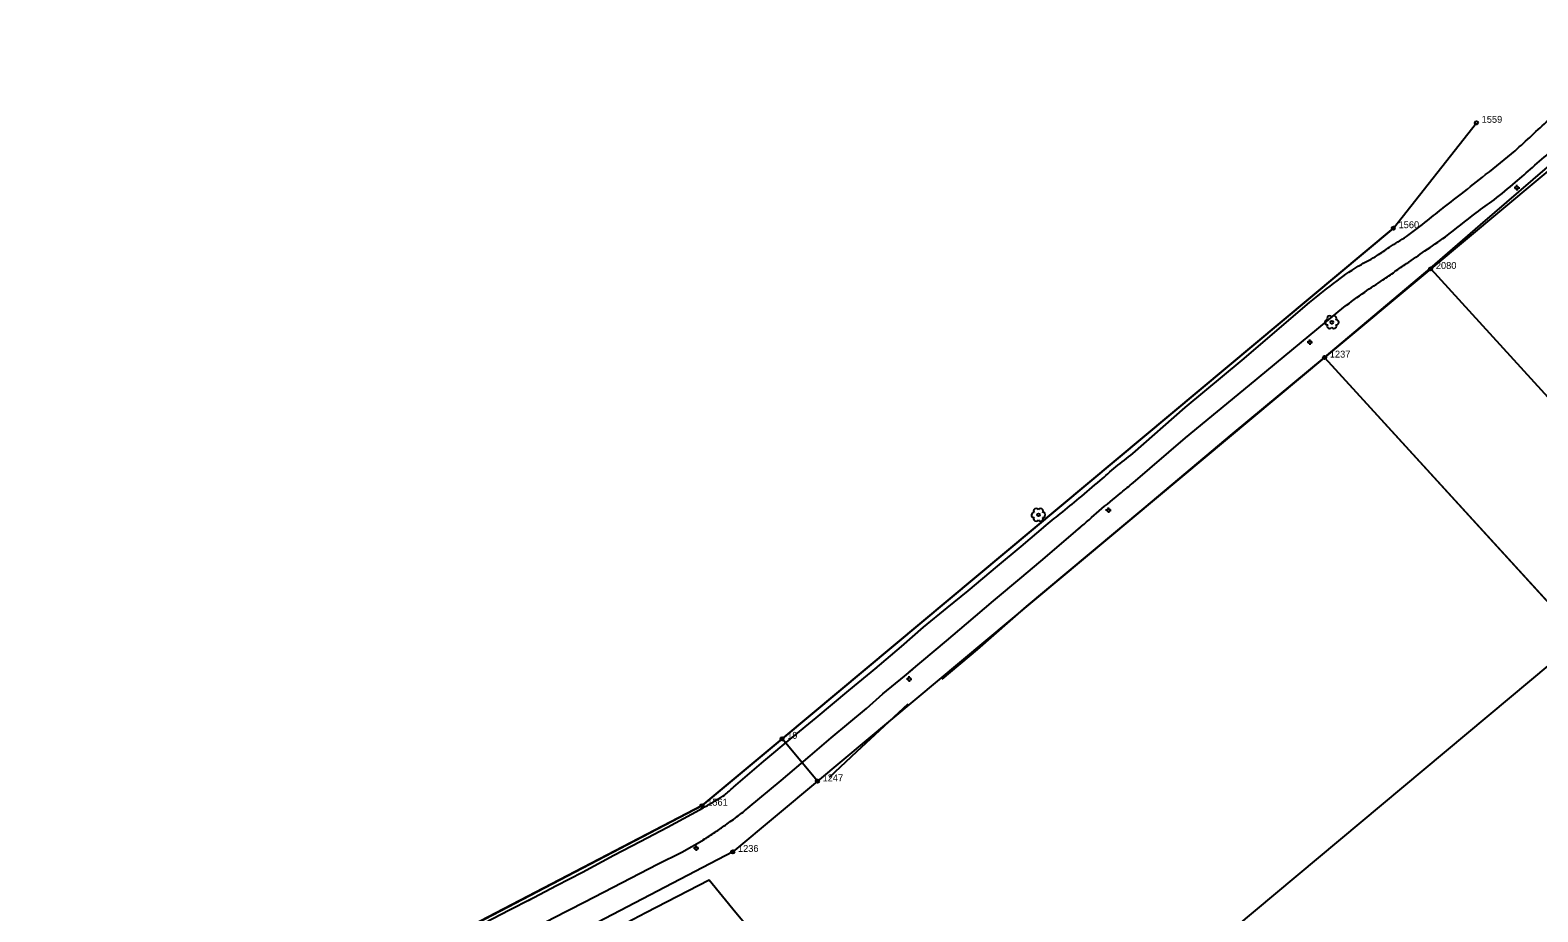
# Model space of a CAD drawing. Extents: x 1517693 to 1518189, y 6494860 to 6495280.
# Drawn here: x 1517718.2 to 1517936.6, y 6495102.4 to 6495230.1 of the extents above; entities that cross this region are included whole.
import ezdxf

# ---------------------------------------------------------------- set-up
doc = ezdxf.new("R2010")
doc.units = 0
for name, color, linetype in [('gc_vag', 7, 'Continuous'), ('grans', 7, 'Continuous'), ('granspunkt', 7, 'Continuous'), ('granspunkt_text', 7, 'Continuous'), ('hack', 7, 'Continuous'), ('kvartersgrans', 7, 'Continuous'), ('kvartersgrans_utan_fastgr', 7, 'Continuous'), ('lovtrad', 7, 'Continuous'), ('staket', 7, 'Continuous'), ('stolpe_belysning', 7, 'Continuous')]:
    doc.layers.add(name, color=color, linetype=linetype)

msp = doc.modelspace()

# ---------------------------------------------------------------- linework, layer by layer
at = {"layer": 'gc_vag'}
for points in [[(1517877.91, 6495168.79), (1517885.48, 6495175.44), (1517893.74, 6495182.28), (1517903.48, 6495190.65)], [(1517877.95, 6495164.55), (1517885.53, 6495171.07), (1517894.79, 6495178.7), (1517908.48, 6495189.97)], [(1517840.59, 6495137.59), (1517844.4, 6495140.81), (1517847.59, 6495143.61), (1517851, 6495146.4), (1517854.04, 6495148.9), (1517858.32, 6495152.45), (1517861.73, 6495155.32), (1517865.28, 6495158.33)], [(1517845.55, 6495137.12), (1517850.93, 6495141.65), (1517853.83, 6495144.08), (1517857.74, 6495147.41), (1517861.84, 6495150.86), (1517865.21, 6495153.72), (1517869.67, 6495157.53), (1517870.39, 6495158.15)], [(1517820.06, 6495120.45), (1517824.46, 6495124.2), (1517828.56, 6495127.61), (1517832.04, 6495130.48), (1517836.79, 6495134.43), (1517840.81, 6495137.77)], [(1517822.19, 6495117.44), (1517826.97, 6495121.41), (1517831.17, 6495124.97), (1517834.22, 6495127.58), (1517839.33, 6495131.82), (1517841.72, 6495133.96), (1517844.83, 6495136.53), (1517845.99, 6495137.48)], [(1517790.33, 6495104.03), (1517794.43, 6495106.16), (1517798.2, 6495108.12), (1517802.73, 6495110.59), (1517806.54, 6495112.54), (1517810.49, 6495114.65), (1517815.16, 6495117.15)], [(1517789.99, 6495099.37), (1517794, 6495101.48), (1517798.46, 6495103.77), (1517802.62, 6495105.94), (1517809.04, 6495109.25), (1517812.59, 6495111.02), (1517815.82, 6495112.87)], [(1517764.88, 6495090.69), (1517769.35, 6495093.03), (1517773.3, 6495095.1), (1517776.31, 6495096.66), (1517781.06, 6495099.2), (1517783.99, 6495100.76), (1517787.62, 6495102.64), (1517790.66, 6495104.2)]]:
    msp.add_lwpolyline(points, dxfattribs=at)
for points in [[(1517908.48, 6495189.97), (1517911.48, 6495192.18), (1517914.11, 6495193.92), (1517915.85, 6495195.13), (1517917.53, 6495196.29), (1517920.21, 6495198.13), (1517923.16, 6495200.18), (1517927.63, 6495203.66), (1517930.21, 6495205.55), (1517933.32, 6495208.08), (1517935.79, 6495210.24), (1517938.53, 6495212.61), (1517940.37, 6495214.19), (1517943, 6495216.82), (1517944.9, 6495218.45)], [(1517922.49, 6495204.07), (1517925.48, 6495206.4), (1517929, 6495209.19), (1517933.26, 6495212.66), (1517938.11, 6495217.09), (1517939.63, 6495218.4)], [(1517903.48, 6495190.65), (1517907.48, 6495193.81), (1517911, 6495196.18), (1517913.27, 6495197.45), (1517915.06, 6495198.66), (1517917.53, 6495200.24), (1517920.58, 6495202.55), (1517922.9, 6495204.4)], [(1517865.07, 6495158.15), (1517867.4, 6495160.05), (1517870.12, 6495162.3), (1517873.16, 6495164.87), (1517875.45, 6495166.83), (1517877.91, 6495168.79)], [(1517870.11, 6495157.91), (1517873.02, 6495160.45), (1517876.24, 6495163.13), (1517877.95, 6495164.55)], [(1517814.84, 6495116.98), (1517816.51, 6495117.91), (1517817.74, 6495118.64), (1517818.75, 6495119.29), (1517820.06, 6495120.45)], [(1517815.66, 6495112.78), (1517817.41, 6495113.92), (1517818.9, 6495114.94), (1517820.75, 6495116.28), (1517822.6, 6495117.77)]]:
    msp.add_spline(points, degree=3, dxfattribs=at)
at = {"layer": 'grans'}
for p, q in [((1517962.44, 6495230.13), (1517921.04, 6495195.52)), ((1517915.64, 6495201.43), (1517927.67, 6495216.7)), ((1517827.1, 6495127.44), (1517915.64, 6495201.43)), ((1517921.04, 6495195.52), (1517905.68, 6495182.68)), ((1517905.68, 6495182.68), (1517832.22, 6495121.28)), ((1517905.68, 6495182.68), (1517942.78, 6495142.01)), ((1517942.78, 6495142.01), (1517887.66, 6495095.94)), ((1517815.51, 6495117.75), (1517827.1, 6495127.44)), ((1517832.22, 6495121.28), (1517827.1, 6495127.44)), ((1517832.22, 6495121.28), (1517819.97, 6495111.05)), ((1517760.41, 6495089.02), (1517815.51, 6495117.75)), ((1517819.97, 6495111.05), (1517718.21, 6495058))]:
    msp.add_line(p, q, dxfattribs=at)
at = {"layer": 'granspunkt'}
for centre in [(1517927.67, 6495216.7), (1517915.64, 6495201.43), (1517921.04, 6495195.52), (1517905.68, 6495182.68), (1517827.1, 6495127.44), (1517832.22, 6495121.28), (1517815.51, 6495117.75), (1517819.97, 6495111.05)]:
    msp.add_circle(centre, 0.237, dxfattribs=at)
at = {"layer": 'hack'}
msp.add_line((1517928.27, 6495201.92), (1517939.69, 6495211.77), dxfattribs=at)
for points in [[(1517905.67, 6495182.7), (1517920.95, 6495195.6), (1517928.27, 6495201.92)], [(1517879.54, 6495160.85), (1517892.35, 6495171.65), (1517905.67, 6495182.7)], [(1517862.49, 6495146.61), (1517868.38, 6495151.53), (1517879.54, 6495160.85)], [(1517850.27, 6495136.09), (1517855.4, 6495140.4), (1517862.49, 6495146.61)], [(1517845.3, 6495132.45), (1517841.19, 6495128.65), (1517837.9, 6495125.54), (1517833.91, 6495121.81)]]:
    msp.add_lwpolyline(points, dxfattribs=at)
at = {"layer": 'kvartersgrans'}
for p, q in [((1517962.44, 6495230.13), (1517921.04, 6495195.52)), ((1517915.64, 6495201.43), (1517927.67, 6495216.7)), ((1517819.97, 6495111.05), (1517718.21, 6495058))]:
    msp.add_line(p, q, dxfattribs=at)
for points in [[(1517915.64, 6495201.43), (1517827.1, 6495127.44), (1517815.51, 6495117.75), (1517760.41, 6495089.02)], [(1517905.68, 6495182.68), (1517832.22, 6495121.28), (1517819.97, 6495111.05)], [(1517905.68, 6495182.68), (1517942.78, 6495142.01), (1518054.69, 6495019.3)]]:
    msp.add_lwpolyline(points, dxfattribs=at)
at = {"layer": 'kvartersgrans_utan_fastgr'}
msp.add_line((1517921.04, 6495195.52), (1518074.11, 6495027.69), dxfattribs=at)
at = {"layer": 'lovtrad'}
for centre in [(1517906.72, 6495187.79), (1517864.22, 6495159.89)]:
    msp.add_circle(centre, 0.2, dxfattribs=at)
for centre, start, end in [((1517906.08, 6495187.79), 89.5389, 268.9887), ((1517906.4, 6495188.35), 29.1347, 212.3057), ((1517906.4, 6495187.24), 150.5831, 330.865), ((1517907.03, 6495188.35), 329.1331, 150.8613), ((1517907.03, 6495187.24), 209.1844, 30.8583), ((1517907.35, 6495187.79), 269.1508, 90.8733), ((1517863.59, 6495159.88), 89.5389, 268.9887), ((1517863.9, 6495160.44), 29.1347, 212.3057), ((1517863.9, 6495159.34), 150.5831, 330.865), ((1517864.54, 6495160.44), 329.1331, 150.8613), ((1517864.54, 6495159.34), 209.1844, 30.8583), ((1517864.86, 6495159.89), 269.1508, 90.8733)]:
    msp.add_arc(centre, 0.366, start, end, dxfattribs=at)
at = {"layer": 'staket'}
msp.add_lwpolyline([(1517827.55, 6495093.72), (1517820.39, 6495102.2), (1517816.53, 6495106.95), (1517807.35, 6495102.2), (1517790.87, 6495093.51)], dxfattribs=at)
at = {"layer": 'stolpe_belysning'}
for p, q in [((1517933.33, 6495207.29), (1517933.13, 6495207.29)), ((1517933.53, 6495207.49), (1517933.53, 6495207.69)), ((1517933.53, 6495207.09), (1517933.53, 6495206.89)), ((1517933.73, 6495207.29), (1517933.93, 6495207.29)), ((1517903.53, 6495185.11), (1517903.53, 6495185.31)), ((1517903.33, 6495184.91), (1517903.13, 6495184.91)), ((1517903.53, 6495184.71), (1517903.53, 6495184.51)), ((1517903.73, 6495184.91), (1517903.93, 6495184.91)), ((1517874.16, 6495160.56), (1517873.96, 6495160.56)), ((1517874.36, 6495160.76), (1517874.36, 6495160.96)), ((1517874.36, 6495160.36), (1517874.36, 6495160.16)), ((1517874.56, 6495160.56), (1517874.76, 6495160.56)), ((1517845.32, 6495136.1), (1517845.12, 6495136.1)), ((1517845.52, 6495136.3), (1517845.52, 6495136.5)), ((1517845.52, 6495135.9), (1517845.52, 6495135.7)), ((1517845.72, 6495136.1), (1517845.92, 6495136.1)), ((1517814.46, 6495111.6), (1517814.26, 6495111.6)), ((1517814.66, 6495111.8), (1517814.66, 6495112)), ((1517814.66, 6495111.4), (1517814.66, 6495111.2)), ((1517814.86, 6495111.6), (1517815.06, 6495111.6))]:
    msp.add_line(p, q, dxfattribs=at)
for centre in [(1517933.53, 6495207.29), (1517903.53, 6495184.91), (1517874.36, 6495160.56), (1517845.52, 6495136.1), (1517814.66, 6495111.6)]:
    msp.add_circle(centre, 0.2, dxfattribs=at)

# ---------------------------------------------------------------- texts
at = {"layer": 'granspunkt_text'}
for s, p in [('1559', (1517928.42, 6495216.7)), ('1560', (1517916.39, 6495201.43)), ('2080', (1517921.79, 6495195.52)), ('1237', (1517906.43, 6495182.68)), ('19', (1517827.85, 6495127.44)), ('1247', (1517832.97, 6495121.28)), ('1561', (1517816.26, 6495117.75)), ('1236', (1517820.72, 6495111.05))]:
    msp.add_text(s, height=1, dxfattribs=at).set_placement(p)

doc.saveas('drawing.dxf')
